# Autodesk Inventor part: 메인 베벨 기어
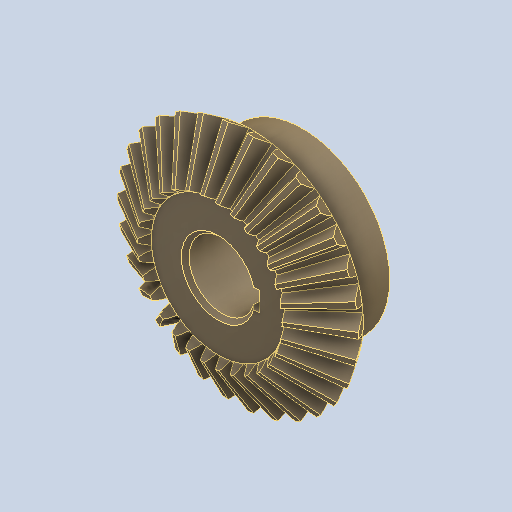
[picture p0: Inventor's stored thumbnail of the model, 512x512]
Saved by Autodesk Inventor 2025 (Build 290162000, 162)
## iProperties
Created: 2024-07
Part Number: 메인 베벨 기어
Material: 강철, 탄소
Document SubType Name: Modeling
Designer: 학생
Density: 7.87 g/cm^3
Appearance: 기본값
Author: jhkim
Revision Number: 1
Sending System: Autodesk Inventor 2025
Preprocessor: ST-DEVELOPER v20
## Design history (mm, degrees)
feature "Solid1"
node "솔리드1"
